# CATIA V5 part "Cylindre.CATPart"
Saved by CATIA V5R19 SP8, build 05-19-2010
Part number: Cylindre
Publications: "H", "rp", "e"
Bounding box of the stored display mesh (mm): x -40 to 40, y -40 to 40, z 0 to 100
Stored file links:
  C:\Users\ThinkMotion\Desktop\EU_thinkMotion\iao\IAO_MMS_Groupe3\evulliez\evulliez\evulliez\Mecanisme\Cylindre.CATPart
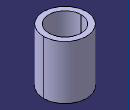
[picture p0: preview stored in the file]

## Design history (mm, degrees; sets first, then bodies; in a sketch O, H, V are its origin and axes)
Parameters
  H = 100 mm
  rp = 30 mm
  e = 10 mm
Body1 (main body)
  Point1: (0, 0, 0)
  Line1: type PtDir, RefPoint Point1, Direction (0, 0, 1), Start 0, End 100 {= H}
  Sketch1 on xy-plane, origin (0, 0, 0), H (1, 0, 0), V (0, 1, 0)
    circle A1 centre (0, 0) radius 30
    point P1 (0, 0)
    circle A2 centre (0, 0) radius 40
    point P2 (0, 0)
    reference projected point E1 (0, 0) from Point1
    reference projected point E2 (0, 0) from Point1
    radius A1 = 30 {= rp}
    radius A2 = 40 {= rp +e}
    coincidence: E1 P2, E2 P1
  Pad1: profile Sketch1, direction (0, 0, 1), length 100 {= H}
  Sketch2 on xy-plane, origin (0, 0, 0), H (1, 0, 0), V (0, 1, 0)
    circle A1 centre (0, 0) radius 30
    point P1 (0, 0)
    reference projected point E1 (0, 0) from Point1
    radius A1 = 30 {= rp}
    coincidence: E1 P1
  Pad2: profile Sketch2, direction (0, 0, 1), length 10 {= e}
